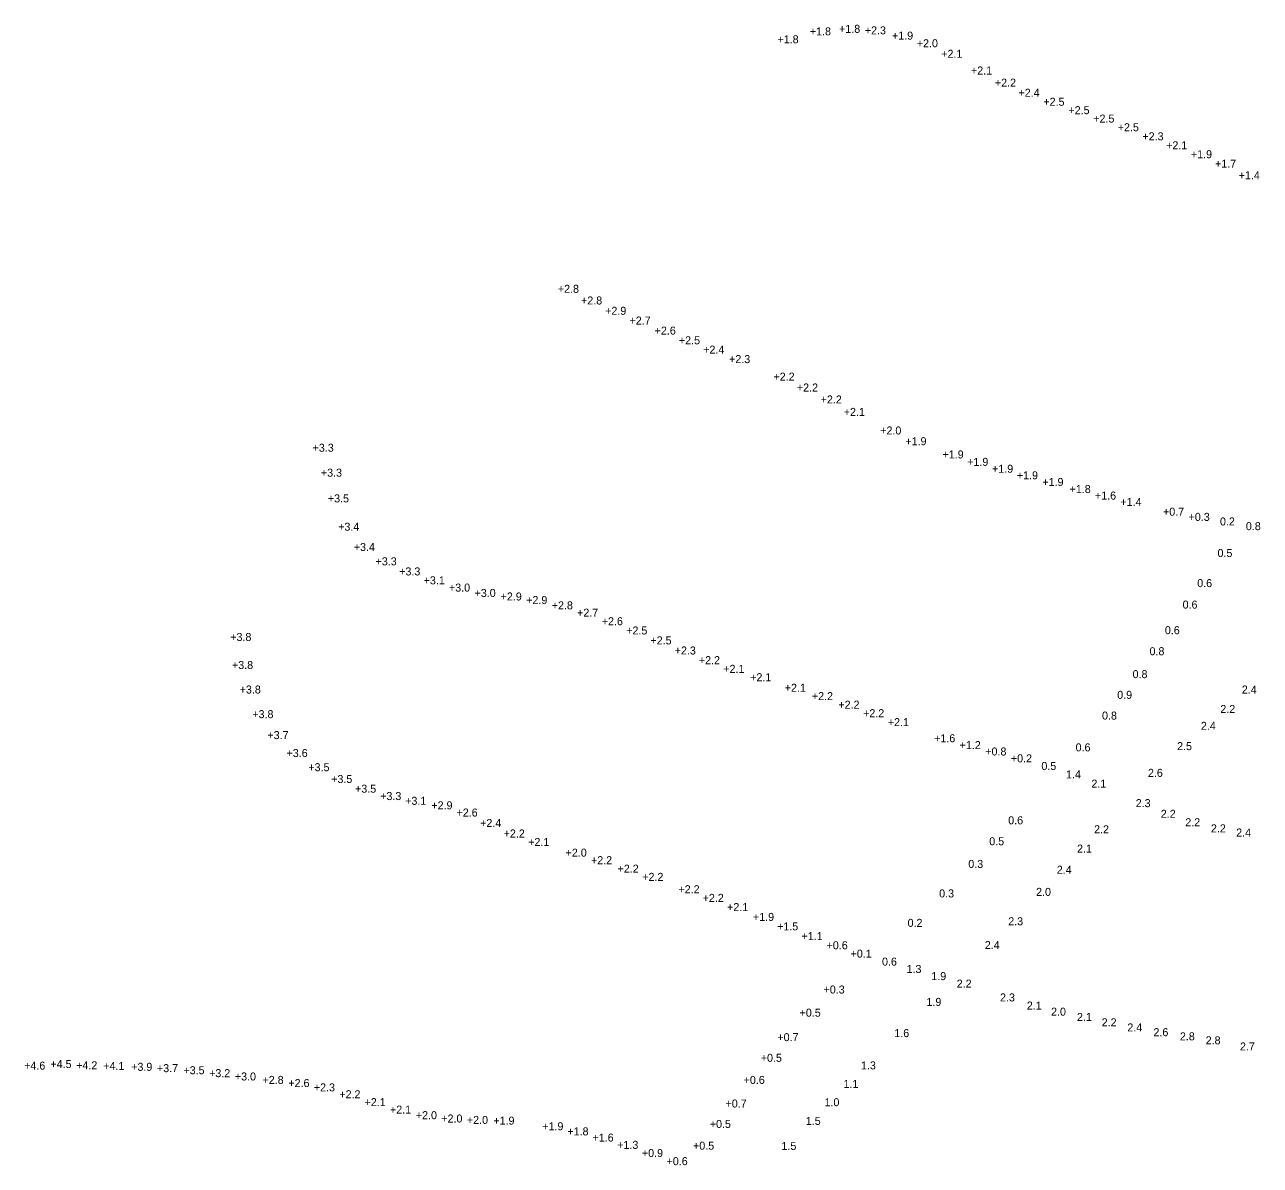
# Model space of a CAD drawing. Extents: x 837127 to 848654, y 3074248 to 3079868.
# Drawn here: x 842723 to 843205.5, y 3079026.6 to 3079471.8 of the extents above; entities that cross this region are included whole.
import ezdxf

# ---------------------------------------------------------------- set-up
doc = ezdxf.new("R2010")
doc.units = 0
doc.layers.add('V-HYDS-SOUN', color=7, linetype='Continuous')

msp = doc.modelspace()

# ---------------------------------------------------------------- texts
at = {"layer": 'V-HYDS-SOUN'}
for s, p in [('+1.8 ', (843016.94, 3079464.53)), ('+1.8 ', (843029.58, 3079467.61)), ('+1.8 ', (843040.99, 3079468.6)), ('+2.3 ', (843051.04, 3079468)), ('+1.9 ', (843061.65, 3079465.95)), ('+2.0 ', (843071.34, 3079462.98)), ('+2.1 ', (843080.89, 3079458.86)), ('+2.1 ', (843092.49, 3079452.34)), ('+2.2 ', (843101.82, 3079447.58)), ('+2.4 ', (843111.03, 3079443.65)), ('+2.5 ', (843120.75, 3079440.14)), ('+2.5 ', (843130.54, 3079436.85)), ('+2.5 ', (843140.24, 3079433.57)), ('+2.5 ', (843149.8, 3079430.19)), ('+2.3 ', (843159.42, 3079426.64)), ('+2.1 ', (843168.7, 3079423.15)), ('+1.9 ', (843178.36, 3079419.66)), ('+1.7 ', (843187.79, 3079415.97)), ('+1.4 ', (843197.01, 3079411.43)), ('+2.8 ', (842931.18, 3079367.12)), ('+2.8 ', (842940.23, 3079362.57)), ('+2.9 ', (842949.64, 3079358.54)), ('+2.7 ', (842959.17, 3079354.74)), ('+2.6 ', (842968.97, 3079350.8)), ('+2.5 ', (842978.45, 3079347.03)), ('+2.4 ', (842987.92, 3079343.4)), ('+2.3 ', (842998.04, 3079339.69)), ('+2.2 ', (843015.36, 3079332.84)), ('+2.2 ', (843024.51, 3079328.6)), ('+2.2 ', (843033.79, 3079323.93)), ('+2.1 ', (843042.82, 3079319.07)), ('+2.0 ', (843057.05, 3079311.82)), ('+3.3 ', (842835.41, 3079305.09)), ('+1.9 ', (843066.87, 3079307.63)), ('+1.9 ', (843081.38, 3079302.47)), ('+3.3 ', (842838.65, 3079295.35)), ('+1.9 ', (843091.01, 3079299.58)), ('+1.9 ', (843100.72, 3079296.89)), ('+1.9 ', (843110.4, 3079294.33)), ('+1.9 ', (843120.36, 3079291.72)), ('+1.8 ', (843130.99, 3079288.95)), ('+1.6 ', (843140.9, 3079286.42)), ('+3.5 ', (842841.38, 3079285.31)), ('+1.4 ', (843150.82, 3079283.95)), ('+0.7 ', (843167.48, 3079280.11)), ('+0.3 ', (843177.46, 3079278.1)), ('0.2', (843189.71, 3079276.32)), ('+3.4 ', (842845.39, 3079274.25)), ('0.8', (843199.82, 3079274.48)), ('+3.4 ', (842851.5, 3079266.33)), ('0.5', (843188.75, 3079263.99)), ('+3.3 ', (842860, 3079260.74)), ('+3.3 ', (842869.23, 3079256.81)), ('+3.1 ', (842878.78, 3079253.32)), ('0.6', (843180.83, 3079252.24)), ('+3.0 ', (842888.67, 3079250.5)), ('+3.0 ', (842898.65, 3079248.4)), ('+2.9 ', (842908.84, 3079247.03)), ('+2.9 ', (842918.82, 3079245.63)), ('+2.8 ', (842928.8, 3079243.56)), ('0.6', (843175.12, 3079243.86)), ('+2.7 ', (842938.69, 3079240.7)), ('+2.6 ', (842948.33, 3079237.37)), ('+2.5 ', (842957.87, 3079233.76)), ('0.6', (843168.2, 3079233.87)), ('+3.8 ', (842803.27, 3079231.23)), ('+2.5 ', (842967.33, 3079229.89)), ('+2.3 ', (842976.8, 3079225.95)), ('0.8', (843162.21, 3079225.66)), ('+3.8 ', (842803.94, 3079220.28)), ('+2.2 ', (842986.23, 3079222.17)), ('+2.1 ', (842995.78, 3079218.78)), ('+2.1 ', (843006.28, 3079215.51)), ('0.8', (843155.59, 3079216.72)), ('+3.8 ', (842806.94, 3079210.71)), ('+2.1 ', (843019.77, 3079211.39)), ('0.9', (843149.59, 3079208.64)), ('2.4', (843198.25, 3079210.7)), ('+2.2 ', (843030.37, 3079208.14)), ('+2.2 ', (843040.71, 3079204.78)), ('+3.8 ', (842811.88, 3079201.09)), ('+2.2 ', (843050.37, 3079201.47)), ('0.8', (843143.66, 3079200.54)), ('2.2', (843189.85, 3079203.12)), ('+2.1 ', (843060.01, 3079197.97)), ('2.4', (843182.27, 3079196.54)), ('+3.7 ', (842817.78, 3079192.92)), ('+1.6 ', (843078.1, 3079191.69)), ('+3.6 ', (842825.24, 3079185.92)), ('+1.2 ', (843088.06, 3079189.02)), ('+0.8 ', (843098.07, 3079186.52)), ('0.6', (843133.34, 3079188.12)), ('2.5', (843172.97, 3079188.61)), ('+3.5 ', (842833.75, 3079180.39)), ('+0.2 ', (843108.07, 3079183.84)), ('0.5', (843119.98, 3079180.87)), ('+3.5 ', (842842.67, 3079175.79)), ('1.4', (843129.59, 3079177.58)), ('2.6', (843161.58, 3079178.18)), ('+3.5 ', (842851.98, 3079171.99)), ('2.1', (843139.51, 3079173.98)), ('+3.3 ', (842861.81, 3079169.12)), ('+3.1 ', (842871.56, 3079167.27)), ('+2.9 ', (842881.79, 3079165.51)), ('2.3', (843156.81, 3079166.36)), ('+2.6 ', (842891.61, 3079162.69)), ('2.2', (843166.6, 3079162.19)), ('+2.4 ', (842900.82, 3079158.6)), ('0.6', (843107.03, 3079159.66)), ('2.2', (843140.56, 3079156.16)), ('2.2', (843176.16, 3079158.9)), ('2.2', (843186.18, 3079156.51)), ('+2.2 ', (842910.02, 3079154.51)), ('+2.1 ', (842919.6, 3079151.2)), ('0.5', (843099.62, 3079151.48)), ('2.4', (843196.05, 3079154.89)), ('+2.0 ', (842934.21, 3079147.04)), ('2.1', (843133.91, 3079148.62)), ('+2.2 ', (842944.12, 3079144.09)), ('0.3', (843091.44, 3079142.63)), ('+2.2 ', (842954.49, 3079140.78)), ('+2.2 ', (842964.15, 3079137.58)), ('2.4', (843126.01, 3079140.36)), ('+2.2 ', (842978.27, 3079132.76)), ('2.0', (843117.91, 3079131.72)), ('+2.2 ', (842987.72, 3079129.38)), ('0.3', (843080.06, 3079131.12)), ('+2.1 ', (842997.25, 3079125.78)), ('+1.9 ', (843007.36, 3079121.95)), ('+1.5 ', (843016.79, 3079118.26)), ('0.2', (843067.74, 3079119.62)), ('2.3', (843107.03, 3079120.25)), ('+1.1 ', (843026.32, 3079114.48)), ('+0.6 ', (843036.11, 3079110.88)), ('+0.1 ', (843045.48, 3079107.62)), ('2.4', (843097.89, 3079110.98)), ('0.6', (843057.75, 3079104.5)), ('1.3', (843067.34, 3079101.63)), ('1.9', (843077, 3079098.83)), ('+0.3 ', (843034.92, 3079093.61)), ('2.2', (843086.91, 3079095.9)), ('1.9', (843075.1, 3079088.78)), ('2.3', (843103.83, 3079090.52)), ('+0.5 ', (843025.57, 3079084.56)), ('2.1', (843114.3, 3079087.35)), ('2.0', (843123.76, 3079084.96)), ('2.1', (843133.86, 3079082.89)), ('2.2', (843143.52, 3079080.8)), ('2.4', (843153.54, 3079078.8)), ('+0.7 ', (843016.9, 3079075.02)), ('1.6', (843062.56, 3079076.6)), ('2.6', (843163.75, 3079076.95)), ('2.8', (843174.06, 3079075.32)), ('2.8', (843184.13, 3079073.78)), ('2.7', (843197.51, 3079071.38)), ('+4.6 ', (842722.8, 3079063.91)), ('+4.5 ', (842733.04, 3079064.52)), ('+4.2 ', (842743.1, 3079064.03)), ('+4.1 ', (842753.69, 3079063.79)), ('+0.5 ', (843010.41, 3079066.96)), ('1.3', (843049.55, 3079063.99)), ('+3.9 ', (842764.59, 3079063.44)), ('+3.7 ', (842774.65, 3079062.92)), ('+3.5 ', (842784.99, 3079062.1)), ('+3.2 ', (842795.01, 3079060.96)), ('+3.0 ', (842805.06, 3079059.68)), ('+2.8 ', (842815.86, 3079058.33)), ('+2.6 ', (842825.95, 3079057.1)), ('+2.3 ', (842835.91, 3079055.4)), ('+0.6 ', (843003.72, 3079058.32)), ('1.1', (843042.72, 3079056.78)), ('+2.2 ', (842845.86, 3079052.73)), ('+2.1 ', (842855.69, 3079049.65)), ('1.0', (843035.3, 3079049.62)), ('+2.1 ', (842865.63, 3079046.73)), ('+2.0 ', (842875.72, 3079044.56)), ('+0.7 ', (842996.65, 3079049.11)), ('+2.0 ', (842885.67, 3079043.26)), ('+2.0 ', (842895.67, 3079042.7)), ('+1.9 ', (842905.99, 3079042.41)), ('+1.9 ', (842925.1, 3079040.24)), ('+0.5 ', (842990.51, 3079041.13)), ('1.5', (843027.99, 3079042.33)), ('+1.8 ', (842934.9, 3079038.23)), ('+1.6 ', (842944.71, 3079035.81)), ('+1.3 ', (842954.35, 3079032.97)), ('+0.5 ', (842983.97, 3079032.65)), ('1.5', (843018.49, 3079032.55)), ('+0.9 ', (842963.99, 3079029.79)), ('+0.6 ', (842973.63, 3079026.61))]:
    msp.add_text(s, height=3.125, dxfattribs=at).set_placement(p)

doc.saveas('drawing.dxf')
